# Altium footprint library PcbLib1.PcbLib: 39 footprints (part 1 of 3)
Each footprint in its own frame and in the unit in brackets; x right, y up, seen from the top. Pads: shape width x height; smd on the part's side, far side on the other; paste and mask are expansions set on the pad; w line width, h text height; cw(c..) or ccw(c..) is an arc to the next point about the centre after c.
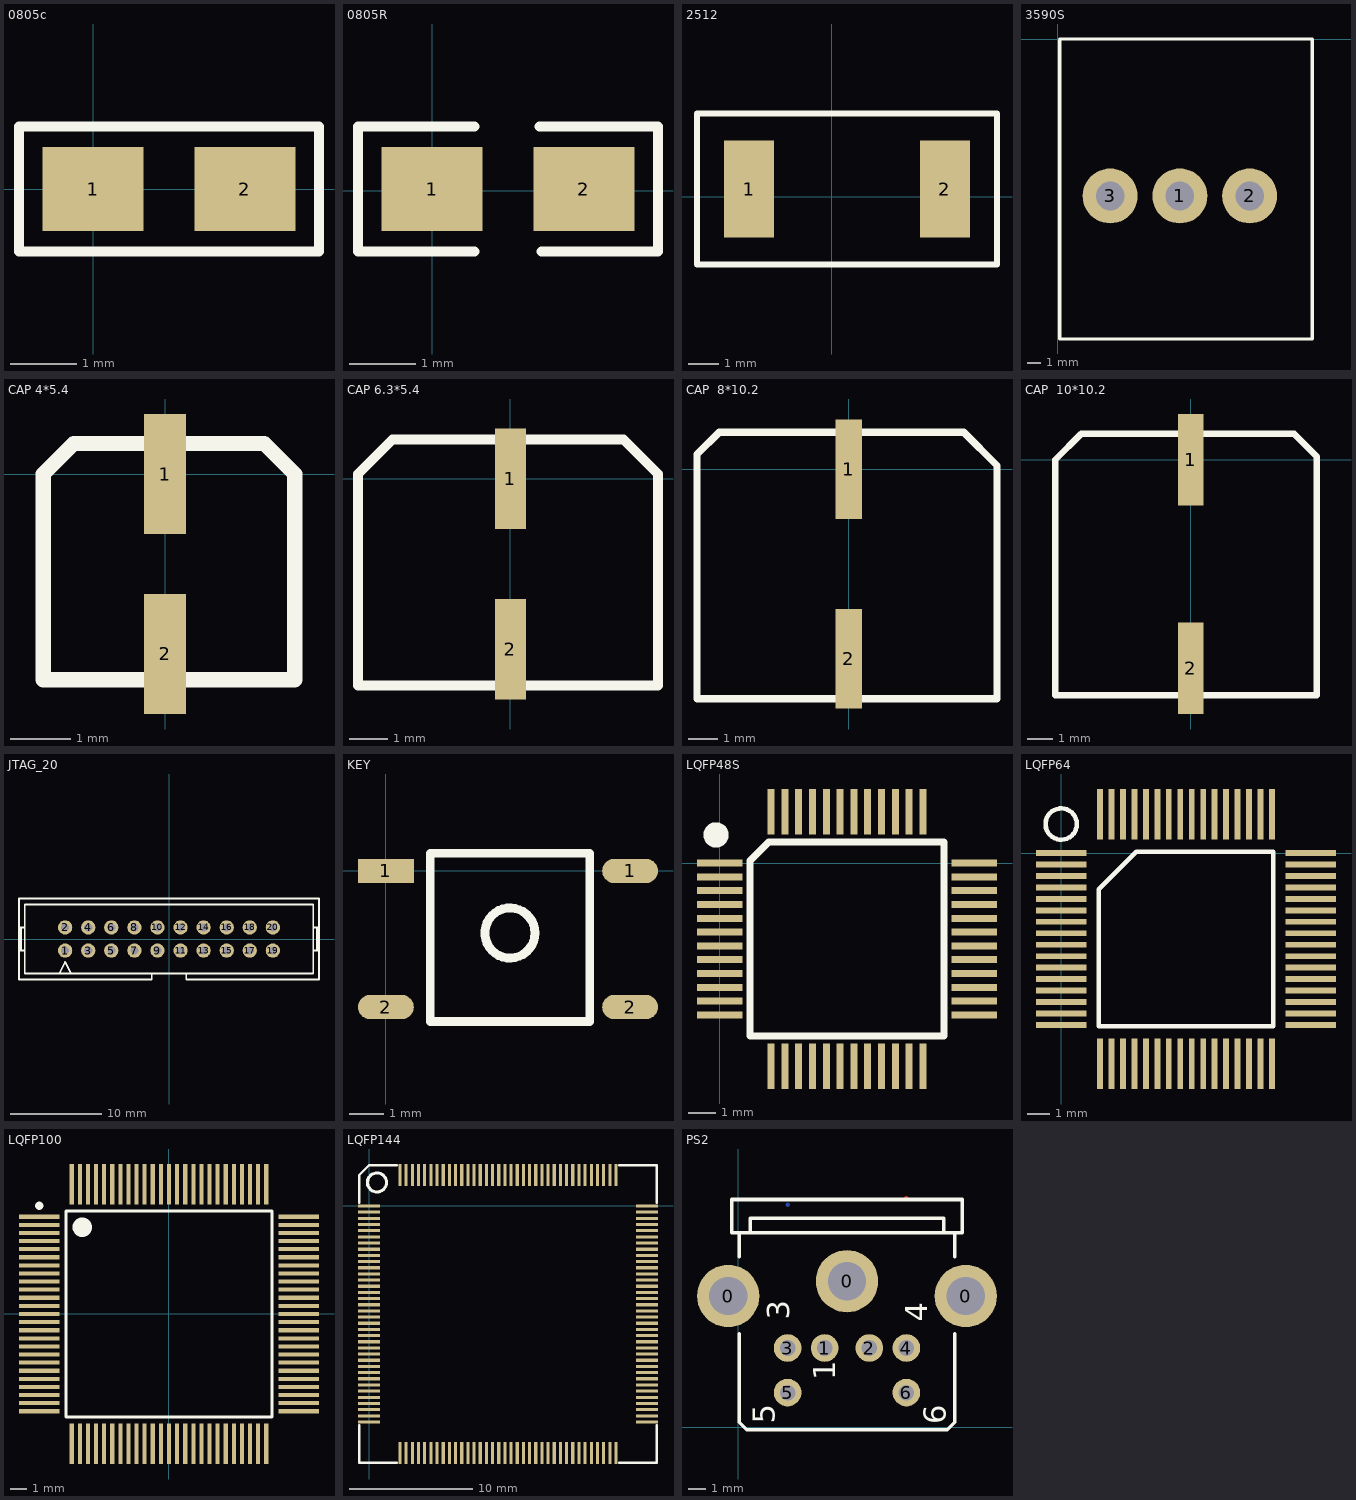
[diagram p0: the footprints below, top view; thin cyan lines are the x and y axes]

## 0805c [mil]
pads (2):
  rect 60x50 smd: 1(0,0) 2(90,0)
Top Overlay:
  lines w6: -44,-37 134,-37 134,37 -44,37 -44,-37
3D body: height 31.39, standoff 0.6, extent 4.64,-24.6 83.38,24.61

## 0805R [mil]
pads (2):
  rect 60x50 smd: 1(0,1) 2(90,1)
Top Overlay:
  lines w6: -44,38 -44,-36 25,-36 ; -43.31,38 25,38 ; 63.78,38 134,38 134,-36 64.96,-36
3D body: height 21.65, standoff 0, extent 4.63,-23.8 83.37,25.81

## 2512 [mm]
pads (2):
  rect 1.65x3.2 smd: 1(-2.732,0.254) 2(3.748,0.254)
Top Overlay:
  lines w0.2: -4.457,-2.246 5.473,-2.246 5.473,2.754 -4.457,2.754 -4.457,0.254 -4.457,-2.246

## 3590S [mm]
pads (3):
  round 4 hole 2.08: 1(8.89,-11.43) 2(13.97,-11.43) 3(3.81,-11.43)
Top Overlay:
  lines w0.254: 0.127,-0.127 0.127,-21.844 18.542,-21.844 18.542,0 0.127,0

## CAP 4*5.4 [mm]
pads (2):
  rect 0.7x2 smd: 1(0,0) 2(0,-3)
Top Overlay:
  lines w0.254: -2.032,-3.429 -2.032,0 -1.524,0.508 1.651,0.508 2.159,0 2.159,-3.429 -2.032,-3.429

## CAP 6.3*5.4 [mm]
pads (2):
  rect 0.8x2.6 smd: 1(0,0) 2(0,-4.4)
Top Overlay:
  lines w0.254: -3.937,-5.334 3.81,-5.334 3.81,0.127 2.921,1.016 -3.048,1.016 -3.937,0.127 -3.937,-5.334

## CAP  8*10.2 [mm]
pads (2):
  rect 0.9x3.4 smd: 1(0,0) 2(0,-6.5)
Top Overlay:
  lines w0.254: -5.207,-7.874 -5.207,0.508 -4.445,1.27 3.937,1.27 5.08,0.127 5.08,-7.874 -5.207,-7.874

## CAP  10*10.2 [mm]
pads (2):
  rect 1x3.6 smd: 1(0,-0.001) 2(0,-8.2)
Top Overlay:
  lines w0.254: -5.334,-9.271 -3.937,-9.271 3.81,-9.271 4.953,-9.271 4.953,-8.128 4.953,0.127 4.064,1.016 -4.318,1.016 -5.334,0 -5.334,-8.128 -5.334,-9.271

## JTAG_20 [mil]
height 149.61
pads (20):
  round 62 hole 35: 1(-450,-50) 2(-450,50) 3(-350,-50) 4(-350,50) 5(-250,-50) 6(-250,50) 7(-150,-50) 8(-150,50) 9(-50,-50) 10(-50,50) 11(50,-50) 12(50,50) 13(150,-50) 14(150,50) 15(250,-50) 16(250,50) 17(350,-50) 18(350,50) 19(450,-50) 20(450,50)
Top Overlay:
  lines w8: -650,-50 -625,-50 ; -650,50 -625,50 ; -641.67,-50 -641.67,50 ; -475,-150 -450,-100 -425,-150 ; -339.57,-175 -75,-175 -75,-150 ; -325,-175 -650,-175 -650,175 650,175 650,-175 325,-175 75,-175 75,-150 ; 625,-50 650,-50 ; 625,50 650,50 ; 641.67,-50 641.67,50 ; -75,-150 -625,-150 -625,150 625,150 625,-150 75,-150 ; -75,-150 75,-150

## KEY [mm]
pads (4):
  rect 1.6x0.7 smd: 1(0,0)
  oval 1.6x0.7 smd: 1(7,0) 2(0,-3.9) 2(7,-3.9)
Top Overlay:
  circle w0.254: c3.556,-1.778 r0.718
  lines w0.254: 1.27,-4.318 1.27,0.508 5.842,0.508 5.842,-4.318 1.27,-4.318

## LQFP48S [mil] "DPIN-0.5"
height 39.37
pads (48):
  rect 65x10 smd: 1(0.42,0.29) 2(0.42,-19.39) 3(0.42,-39.08) 4(0.42,-58.76) 5(0.42,-78.45) 6(0.42,-98.13) 7(0.42,-117.82) 8(0.42,-137.5) 9(0.42,-157.19) 10(0.42,-176.87) 11(0.42,-196.56) 12(0.42,-216.24) 25(362.63,-216.24) 26(362.63,-196.56) 27(362.63,-176.87) 28(362.63,-157.19) 29(362.63,-137.5) 30(362.63,-117.82) 31(362.63,-98.13) 32(362.63,-78.45) 33(362.63,-58.76) 34(362.63,-39.08) 35(362.63,-19.39) 36(362.63,0.29)
  rect 10x65 smd: 13(73.26,-289.08) 14(92.94,-289.08) 15(112.63,-289.08) 16(132.31,-289.08) 17(152,-289.08) 18(171.68,-289.08) 19(191.37,-289.08) 20(211.05,-289.08) 21(230.74,-289.08) 22(250.42,-289.08) 23(270.11,-289.08) 24(289.79,-289.08) 37(289.79,73.13) 38(270.11,73.13) 39(250.42,73.13) 40(230.74,73.13) 41(211.05,73.13) 42(191.37,73.13) 43(171.68,73.13) 44(152,73.13) 45(132.31,73.13) 46(112.63,73.13) 47(92.94,73.13) 48(73.26,73.13)
Top Overlay:
  circle w25: c-4.93,40.29 r5.35
  lines w10: 43.73,-245.77 43.73,3.6 69.95,29.82 319.32,29.82 319.32,-245.77 43.73,-245.77

## LQFP64 [mm] "LQFP64"
height 2
pads (64):
  rect 2.2x0.254 smd: 1(0,0) 2(0,-0.5) 3(0,-1) 4(0,-1.5) 5(0,-2) 6(0,-2.5) 7(0,-3) 8(0,-3.5) 9(0,-4) 10(0,-4.5) 11(0,-5) 12(0,-5.5) 13(0,-6) 14(0,-6.5) 15(0,-7) 16(0,-7.5) 33(10.9,-7.5) 34(10.9,-7) 35(10.9,-6.5) 36(10.9,-6) 37(10.9,-5.5) 38(10.9,-5) 39(10.9,-4.5) 40(10.9,-4) 41(10.9,-3.5) 42(10.9,-3) 43(10.9,-2.5) 44(10.9,-2) 45(10.9,-1.5) 46(10.9,-1) 47(10.9,-0.5) 48(10.9,0)
  rect 0.254x2.2 smd: 17(1.7,-9.2) 18(2.2,-9.2) 19(2.7,-9.2) 20(3.2,-9.2) 21(3.7,-9.2) 22(4.2,-9.2) 23(4.7,-9.2) 24(5.2,-9.2) 25(5.7,-9.2) 26(6.2,-9.2) 27(6.7,-9.2) 28(7.2,-9.2) 29(7.7,-9.2) 30(8.2,-9.2) 31(8.7,-9.2) 32(9.2,-9.2) 49(9.2,1.7) 50(8.7,1.7) 51(8.2,1.7) 52(7.7,1.7) 53(7.2,1.7) 54(6.7,1.7) 55(6.2,1.7) 56(5.7,1.7) 57(5.2,1.7) 58(4.7,1.7) 59(4.2,1.7) 60(3.7,1.7) 61(3.2,1.7) 62(2.7,1.7) 63(2.2,1.7) 64(1.7,1.7)
Top Overlay:
  circle w0.2: c0,1.27 r0.684
  lines w0.2: 1.635,-7.565 1.635,-1.57 3.27,0.065 9.265,0.065 9.265,-7.565 1.635,-7.565

## LQFP100 [mm] "TSQFP, 100-Leads, Body 16.0x16.0mm (max), Pitch 0.50mm, IPC Medium Density"
height 1.5
pads (100):
  rect 2.5x0.254 smd: 1(-8,6) 2(-8,5.5) 3(-8,5) 4(-8,4.5) 5(-8,4) 6(-8,3.5) 7(-8,3) 8(-8,2.5) 9(-8,2) 10(-8,1.5) 11(-8,1) 12(-8,0.5) 13(-8,0) 14(-8,-0.5) 15(-8,-1) 16(-8,-1.5) 17(-8,-2) 18(-8,-2.5) 19(-8,-3) 20(-8,-3.5) 21(-8,-4) 22(-8,-4.5) 23(-8,-5) 24(-8,-5.5) 25(-8,-6) 51(8,-6) 52(8,-5.5) 53(8,-5) 54(8,-4.5) 55(8,-4) 56(8,-3.5) 57(8,-3) 58(8,-2.5) 59(8,-2) 60(8,-1.5) 61(8,-1) 62(8,-0.5) 63(8,0) 64(8,0.5) 65(8,1) 66(8,1.5) 67(8,2) 68(8,2.5) 69(8,3) 70(8,3.5) 71(8,4) 72(8,4.5) 73(8,5) 74(8,5.5) 75(8,6)
  rect 0.254x2.5 smd: 26(-6,-8) 27(-5.5,-8) 28(-5,-8) 29(-4.5,-8) 30(-4,-8) 31(-3.5,-8) 32(-3,-8) 33(-2.5,-8) 34(-2,-8) 35(-1.5,-8) 36(-1,-8) 37(-0.5,-8) 38(0,-8) 39(0.5,-8) 40(1,-8) 41(1.5,-8) 42(2,-8) 43(2.5,-8) 44(3,-8) 45(3.5,-8) 46(4,-8) 47(4.5,-8) 48(5,-8) 49(5.5,-8) 50(6,-8) 76(6,8) 77(5.5,8) 78(5,8) 79(4.5,8) 80(4,8) 81(3.5,8) 82(3,8) 83(2.5,8) 84(2,8) 85(1.5,8) 86(1,8) 87(0.5,8) 88(0,8) 89(-0.5,8) 90(-1,8) 91(-1.5,8) 92(-2,8) 93(-2.5,8) 94(-3,8) 95(-3.5,8) 96(-4,8) 97(-4.5,8) 98(-5,8) 99(-5.5,8) 100(-6,8)
Top Overlay:
  circle w0.6: c-5.35,5.35 r0.3
  circle w0.25: c-8,6.675 r0.125
  lines w0.2: -6.35,-6.35 6.35,-6.35 6.35,6.35 -6.35,6.35 -6.35,-6.35

## LQFP144 [mm]
pads (144):
  rect 1.8x0.254 smd: 1(-0.009,0.001) 2(-0.009,-0.499) 3(-0.009,-0.999) 4(-0.009,-1.499) 5(-0.009,-1.999) 6(-0.009,-2.499) 7(-0.009,-2.999) 8(-0.009,-3.499) 9(-0.009,-3.999) 10(-0.009,-4.499) 11(-0.009,-4.999) 12(-0.009,-5.499) 13(-0.009,-5.999) 14(-0.009,-6.499) 15(-0.009,-6.999) 16(-0.009,-7.499) 17(-0.009,-7.999) 18(-0.009,-8.499) 19(-0.009,-8.999) 20(-0.009,-9.499) 21(-0.009,-9.999) 22(-0.009,-10.499) 23(-0.009,-10.999) 24(-0.009,-11.499) 25(-0.009,-11.999) 26(-0.009,-12.499) 27(-0.009,-12.999) 28(-0.009,-13.499) 29(-0.009,-13.999) 30(-0.009,-14.499) 31(-0.009,-14.999) 32(-0.009,-15.499) 33(-0.009,-15.999) 34(-0.009,-16.499) 35(-0.009,-16.999) 36(-0.009,-17.499) 73(22.491,-17.499) 74(22.491,-16.999) 75(22.491,-16.499) 76(22.491,-15.999) 77(22.491,-15.499) 78(22.491,-14.999) 79(22.491,-14.499) 80(22.491,-13.999) 81(22.491,-13.499) 82(22.491,-12.999) 83(22.491,-12.499) 84(22.491,-11.999) 85(22.491,-11.499) 86(22.491,-10.999) 87(22.491,-10.499) 88(22.491,-9.999) 89(22.491,-9.499) 90(22.491,-8.999) 91(22.491,-8.499) 92(22.491,-7.999) 93(22.491,-7.499) 94(22.491,-6.999) 95(22.491,-6.499) 96(22.491,-5.999) 97(22.491,-5.499) 98(22.491,-4.999) 99(22.491,-4.499) 100(22.491,-3.999) 101(22.491,-3.499) 102(22.491,-2.999) 103(22.491,-2.499) 104(22.491,-1.999) 105(22.491,-1.499) 106(22.491,-0.999) 107(22.491,-0.499) 108(22.491,0.001)
  rect 0.254x1.8 smd: 37(2.491,-19.999) 38(2.991,-19.999) 39(3.491,-19.999) 40(3.991,-19.999) 41(4.491,-19.999) 42(4.991,-19.999) 43(5.491,-19.999) 44(5.991,-19.999) 45(6.491,-19.999) 46(6.991,-19.999) 47(7.491,-19.999) 48(7.991,-19.999) 49(8.491,-19.999) 50(8.991,-19.999) 51(9.491,-19.999) 52(9.991,-19.999) 53(10.491,-19.999) 54(10.991,-19.999) 55(11.491,-19.999) 56(11.991,-19.999) 57(12.491,-19.999) 58(12.991,-19.999) 59(13.491,-19.999) 60(13.991,-19.999) 61(14.491,-19.999) 62(14.991,-19.999) 63(15.491,-19.999) 64(15.991,-19.999) 65(16.491,-19.999) 66(16.991,-19.999) 67(17.491,-19.999) 68(17.991,-19.999) 69(18.491,-19.999) 70(18.991,-19.999) 71(19.491,-19.999) 72(19.991,-19.999) 109(19.991,2.501) 110(19.491,2.501) 111(18.991,2.501) 112(18.491,2.501) 113(17.991,2.501) 114(17.491,2.501) 115(16.991,2.501) 116(16.491,2.501) 117(15.991,2.501) 118(15.491,2.501) 119(14.991,2.501) 120(14.491,2.501) 121(13.991,2.501) 122(13.491,2.501) 123(12.991,2.501) 124(12.491,2.501) 125(11.991,2.501) 126(11.491,2.501) 127(10.991,2.501) 128(10.491,2.501) 129(9.991,2.501) 130(9.491,2.501) 131(8.991,2.501) 132(8.491,2.501) 133(7.991,2.501) 134(7.491,2.501) 135(6.991,2.501) 136(6.491,2.501) 137(5.991,2.501) 138(5.491,2.501) 139(4.991,2.501) 140(4.491,2.501) 141(3.991,2.501) 142(3.491,2.501) 143(2.991,2.501) 144(2.491,2.501)
Top Overlay:
  circle w0.254: c0.624,1.905 r0.773
  lines w0.2: -0.809,-17.749 -0.809,-20.799 2.241,-20.799 ; -0.809,0.251 -0.809,2.501 -0.009,3.301 2.241,3.301 ; 20.241,-20.799 23.291,-20.799 23.291,-17.749 ; 20.241,3.301 23.291,3.301 23.291,0.251

## PCBComponent_1 [mm]

## PS2 [mil]
pads (9):
  round 140 hole 86: 0(-22.67,294.67) 0(244,328) 0(510.67,294.67)
  round 62 hole 35: 1(194,178) 2(294,178) 3(110.67,178) 4(377.33,178) 5(110.67,78) 6(377.33,78)
Top Layer:
  lines w10: 377,514 377.33,513.67
Bottom Layer:
  lines w10: 110.67,499.67 111,500 ; 376.33,77 377.33,78
Top Overlay:
  lines w8: 2.33,209.5 2.33,11.33 19,-5.33 469,-5.33 485.67,11.33 485.67,209.5 ; 2.33,382.72 2.33,436.33 ; 485.67,382.72 485.67,436.33 ; 27.33,436.33 460.67,436.33 ; 27.33,436.33 -14.33,436.33 -14.33,511.33 502.33,511.33 502.33,436.33 460.67,436.33 ; 27.33,436.33 27.33,469.67 460.67,469.67 460.67,436.33
  text "1" at 217.43,105.9 h50
  text "3" at 114.77,241.9 h50
  text "4" at 424.1,236.57 h50
  text "6" at 465.43,7.24 h50
  text "5" at 81.43,8.57 h50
